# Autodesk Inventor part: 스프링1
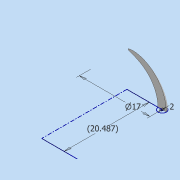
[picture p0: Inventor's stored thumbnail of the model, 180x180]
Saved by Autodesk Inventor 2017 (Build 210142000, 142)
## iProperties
Part Number: 스프링1
Material: 일반
Document SubType Name: Modeling
Designer: MRC
Density: 1 g/cm^3
Appearance: 기본값
Author: MRC
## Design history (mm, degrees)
sketch "스케치1"
  geometry: L1 (0, 0)-(0, -20.487); L2 (0, 0)-(8.5, 0); L3 (0, -20.487)-(8.5, -20.487); C1 r 1 at (8.5, 0)
  constraints: 6 end point, 1 centre point, 1 coincident, 1 horizontal, 1 vertical, 1 vertical alignment
  dimensions: "d0" = 20.48711 distance of L1.start L1.end (derived); "d1" = 17 diameter of L2.end L1; "d2" = 2 diameter of C1
feature "코일1" pitch "d3" = 10; turns "d5" = 5; dims "d4" = 20.48711 (= d0), "d6" = 0, angle "d7" = 90 deg, angle "d8" = 90 deg, "d9" = 0, "d10" = 0
sketch "스케치2"
  geometry: L1 (20.487, 17.5)-(0, 17.5); L2 (0, 17.5)-(0, -17.5); L3 (0, -17.5)-(20.487, -17.5); L4 (20.487, -17.5)-(20.487, 17.5); 2 further points
  constraints: 8 end point, 2 parallel, 1 coincident, 1 horizontal, 1 midpoint, 1 perpendicular
  dimensions: "d11" = 20.48711 distance of L2.end L3.end (= d0); "d12" = 35 distance between parallel lines of L1 L3
extrude "돌출1" sketch "스케치2" stored distance "d13" = 0; taper "d14" = 0 deg
node "솔리드1"
